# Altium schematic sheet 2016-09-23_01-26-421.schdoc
size 383 x 181 mm; SheetNumber: 1; SheetTotal: 1
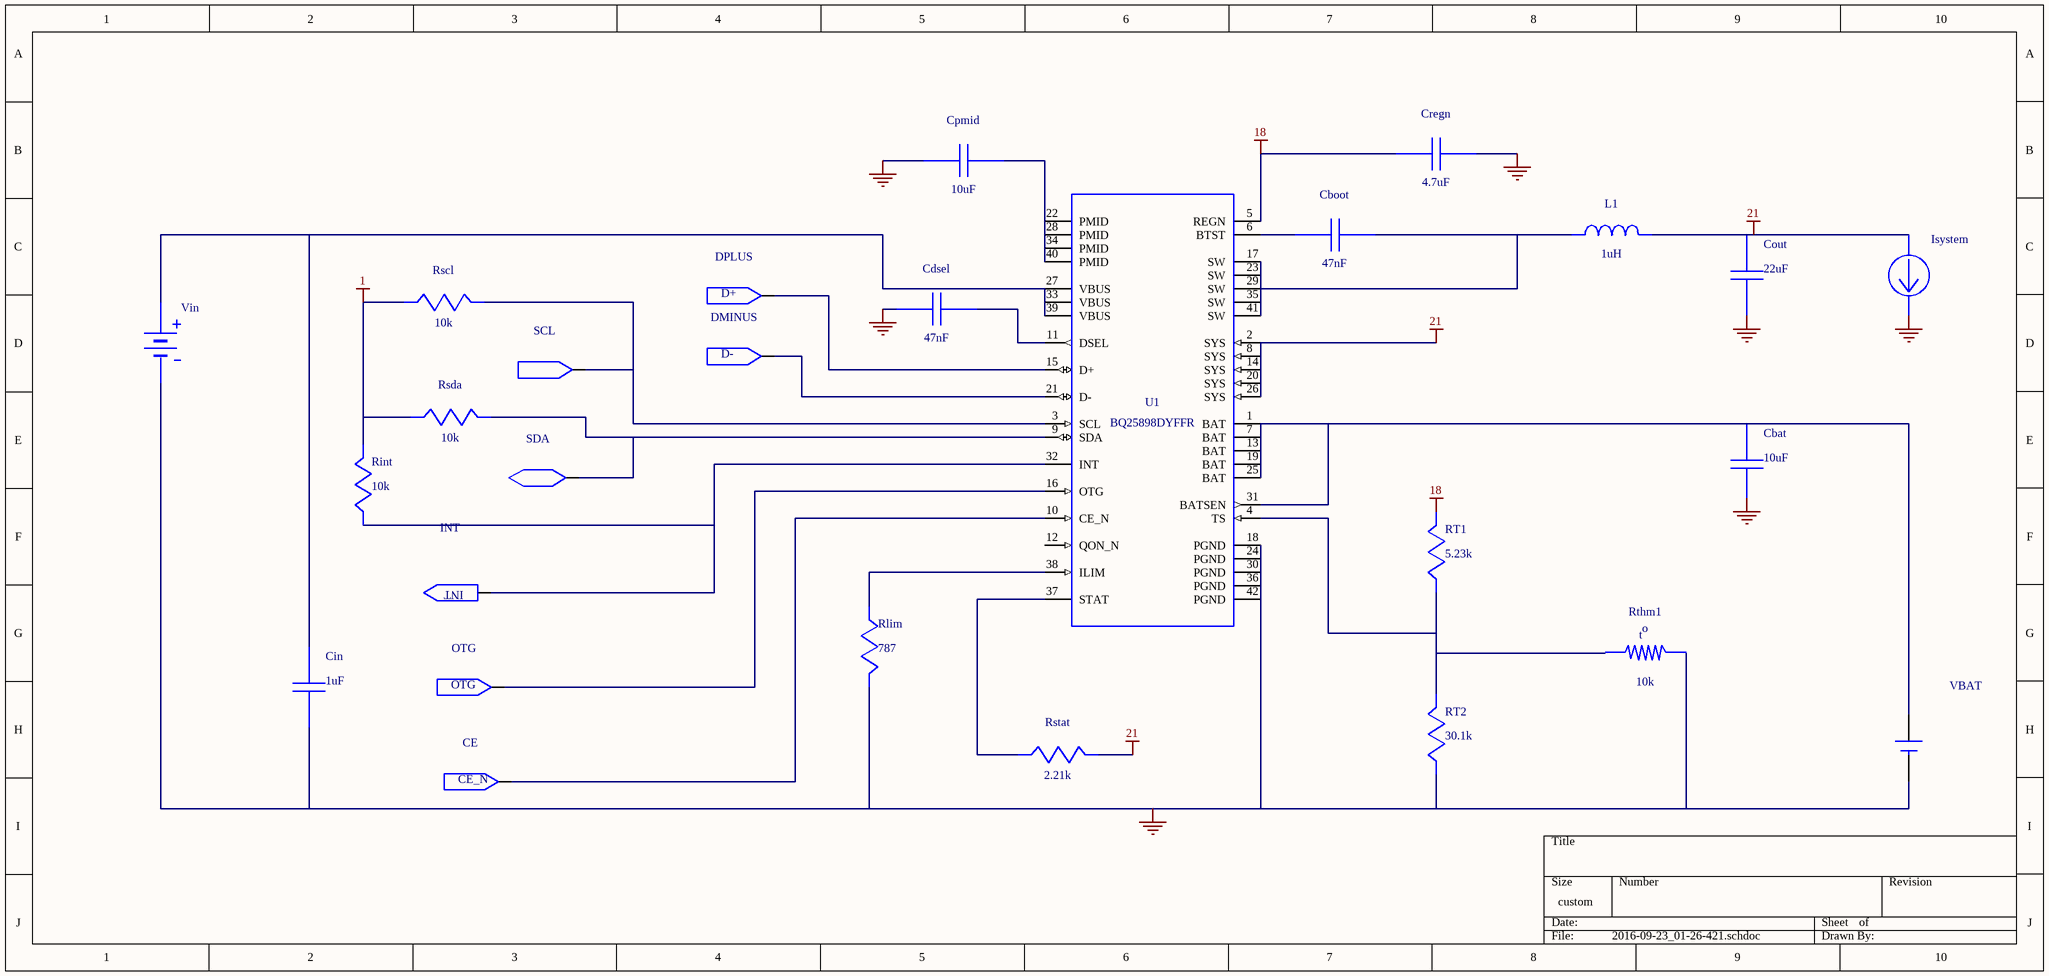
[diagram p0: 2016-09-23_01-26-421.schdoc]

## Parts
Cbat  value 10uF  (hidden comment: GRM219R60J106KE19D)
Cboot  value 47nF  (hidden comment: GRM155R61A473KA01D)
Cdsel  value 47nF  (hidden comment: TMK212B7473KD-T)
CE  WB_CE_N  (value not drawn)
Cin  value 1uF  (hidden comment: GRM188R61A105KA61D)
Cout  value 22uF  (hidden comment: LMK212BJ226MG-T)
Cpmid  value 10uF  (hidden comment: GRM21BR61A106KE19L)
Cregn  value 4.7uF  (hidden comment: GRM21BR61E475KA12L)
DMINUS  WB_DMINUS  (value not drawn)
DPLUS  WB_DPLUS  (value not drawn)
INT  WB_INT_R180  (value not drawn)
Isystem  WB_CURRENT_LOAD  (value not drawn)
L1  value 1uH  (hidden comment: 'VLF252012MT-1R0N')
OTG  WB_OTG  (value not drawn)
Rint  value 10k  (hidden comment: CRCW040210K0FKED)
Rlim  value 787  (hidden comment: CRCW0402787RFKED)
Rscl  value 10k  (hidden comment: CRCW040210K0FKED)
Rsda  value 10k  (hidden comment: CRCW040210K0FKED)
Rstat  value 2.21k  (hidden comment: CRCW04022K21FKED)
RT1  value 5.23k  (hidden comment: CRCW04025K23FKED)
RT2  value 30.1k  (hidden comment: CRCW040230K1FKED)
Rthm1  value 10k  (hidden comment: NCP15XH103E03RC)
SCL  WB_I2C_SCL  (value not drawn)
SDA  WB_I2C_SDA  (value not drawn)
U1  BQ25898DYFFR
VBAT  WB_BATTERY_SINGLE_USFP  (value not drawn)
Vin  WB_BATTERY  (value not drawn)

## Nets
0: Cdsel.2 Cin.2 Cout.2 Cpmid.2 Cregn.2 Isystem.2(-) Rlim.1 RT2.2 U1.18(PGND) U1.24(PGND) U1.30(PGND) U1.36(PGND) U1.42(PGND) VBAT.2(-) Vin.2(-)
1: Rint.1 Rscl.2 Rsda.2
18: Cregn.1 RT1.1 U1.5(REGN)
21: Cout.1 Isystem.1(+) L1.2 Rstat.1 U1.2(SYS) U1.8(SYS) U1.14(SYS) U1.20(SYS) U1.26(SYS)
NetCbat_1: Cbat.1 U1.1(BAT) U1.7(BAT) U1.13(BAT) U1.19(BAT) U1.25(BAT) U1.31(BATSEN) VBAT.1(+)
NetCboot_1: Cboot.1 L1.1 U1.17(SW) U1.23(SW) U1.29(SW) U1.35(SW) U1.41(SW)
NetCboot_2: Cboot.2 U1.6(BTST)
NetCdsel_1: Cdsel.1 U1.11(DSEL)
NetCE_1: CE.1 U1.10(CE_N)
NetCin_1: Cin.1 U1.27(VBUS) U1.33(VBUS) U1.39(VBUS) Vin.1(+)
NetCpmid_1: Cpmid.1 U1.22(PMID) U1.28(PMID) U1.34(PMID) U1.40(PMID)
NetDMINUS_1: DMINUS.1 U1.21(D-)
NetDPLUS_1: DPLUS.1 U1.15(D+)
NetINT_1: INT.1 Rint.2 U1.32(INT)
NetOTG_1: OTG.1 U1.16(OTG)
NetRlim_2: Rlim.2 U1.38(ILIM)
NetRscl_1: Rscl.1 SCL.1 U1.3(SCL)
NetRsda_1: Rsda.1 SDA.1 U1.9(SDA)
NetRstat_2: Rstat.2 U1.37(STAT)
NetRT1_2: RT1.2 RT2.1 U1.4(TS)

Not connected (* = marked no-connect by the designer): Cbat 2; Rthm1 1 2; U1 12(QON_N)

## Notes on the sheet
- (near DPLUS) D+
- (near DMINUS) D-
- (near INT) INT
- (near Rthm1) t
- (near Rthm1) o
- (near OTG) OTG
- (near CE) CE_N
- Labels drawn without touching a wire or pin: 0

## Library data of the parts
Cbat = GRM219R60J106KE19D: GRM219R60J106KE1; Manufacturer Name: MuRata
Cboot = GRM155R61A473KA01D: GRM155R61A473KA0; Manufacturer Name: MuRata
Cdsel = TMK212B7473KD-T: Manufacturer Name: Taiyo Yuden
Cin = GRM188R61A105KA61D: GRM188R61A105KA6; Manufacturer Name: MuRata
Cout = LMK212BJ226MG-T: Manufacturer Name: Taiyo Yuden
Cpmid = GRM21BR61A106KE19L: GRM21BR61A106KE1; Manufacturer Name: MuRata
Cregn = GRM21BR61E475KA12L: GRM21BR61E475KA1; Manufacturer Name: MuRata
L1 = 'VLF252012MT-1R0N': VLF252012MT-1R0N; Manufacturer Name: TDK
Rint Rscl Rsda = CRCW040210K0FKED: Manufacturer Name: Vishay-Dale
Rlim = CRCW0402787RFKED: Manufacturer Name: Vishay-Dale
Rstat = CRCW04022K21FKED: Manufacturer Name: Vishay-Dale
RT1 = CRCW04025K23FKED: Manufacturer Name: Vishay-Dale
RT2 = CRCW040230K1FKED: Manufacturer Name: Vishay-Dale
Rthm1 = NCP15XH103E03RC: Manufacturer Name: MuRata
U1 = BQ25898DYFFR: Manufacturer Name: Texas Instruments
VBAT = WB_BATTERY_SINGLE_USFP: WB_BATTERY_SINGL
